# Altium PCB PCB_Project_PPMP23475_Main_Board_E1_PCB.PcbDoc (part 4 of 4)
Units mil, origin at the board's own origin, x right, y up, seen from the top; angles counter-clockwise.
Board outline 10826.77 x 2559.06 mil, 6 copper layers (Top Layer, Signal Layer 1, Signal Layer 2, Signal Layer 3, Signal Layer 4, Bottom Layer), stack 65.535 mil thick; 162 components, 91 nets, 425 pads, 676 vias.
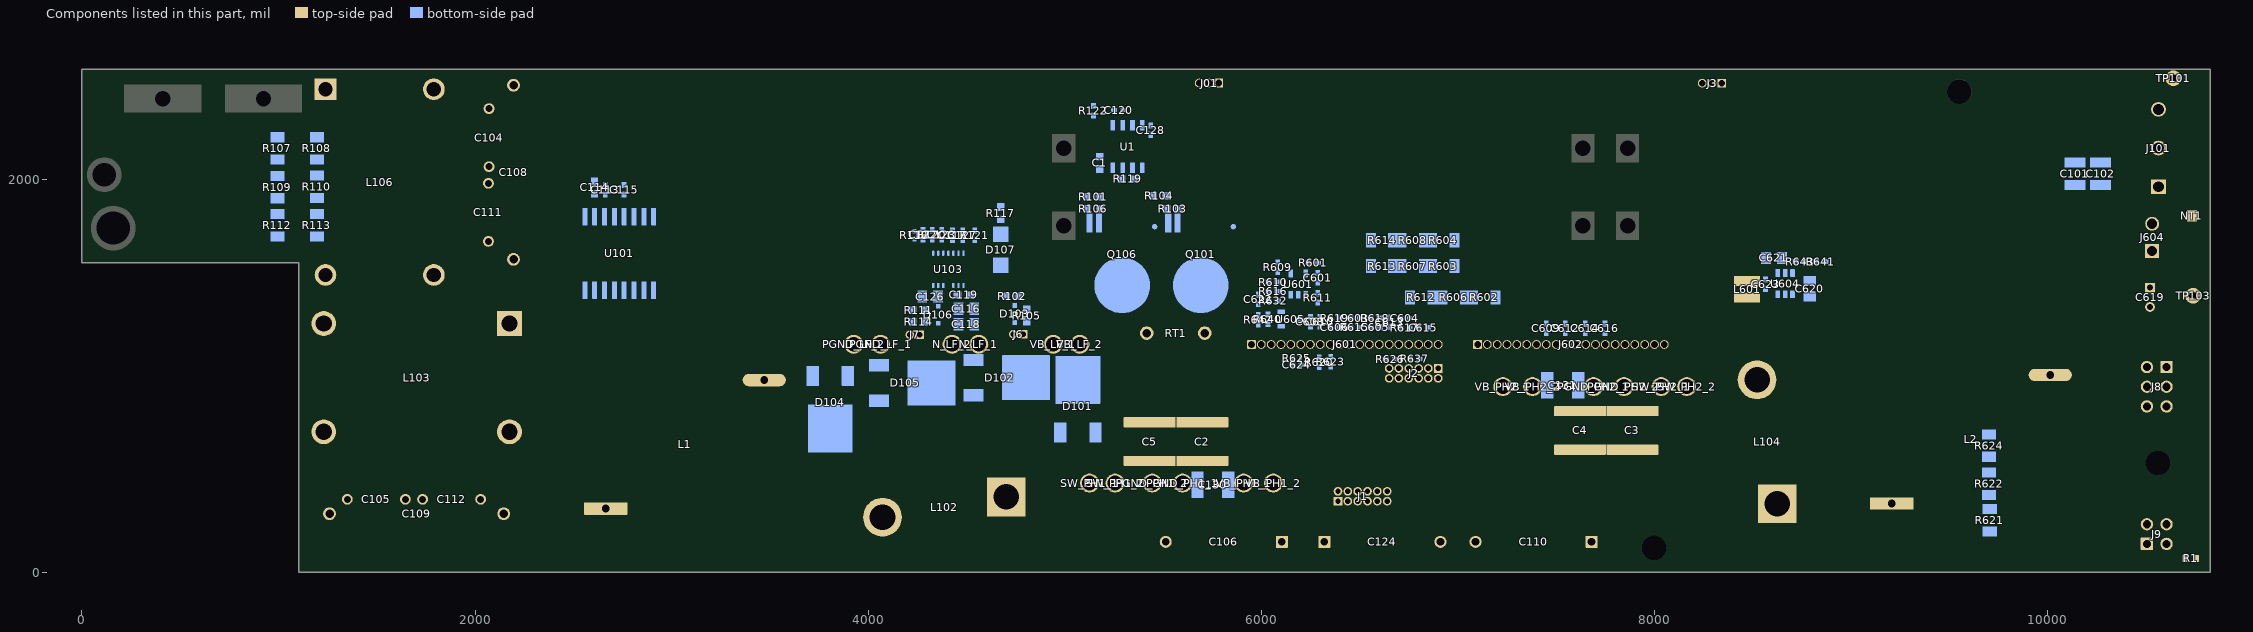
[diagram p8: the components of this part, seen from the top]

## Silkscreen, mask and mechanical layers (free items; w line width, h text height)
Top Overlay:
  circle w5: c7997,124 r118.11
  circle w5: c9551,2446 r118.11
  circle w5: c10562,557 r118.11
  lines w5: 2514.57,1350.53 5113,1350.53 5113,2571 2514.57,2571 2514.57,1350.53 ; 5155.57,1350.91 7754,1350.91 7754,2571.39 5155.57,2571.39 5155.57,1350.91 ; 7745,1350.91 10343.43,1350.91 10343.43,2571.39 7745,2571.39 7745,1350.91
  lines w7: 97.23,2214.15 97.23,2489.74 1081.48,2489.74 1081.48,1804.7 313.76,1804.7 313.76,2214.15 97.23,2214.15 ; 2336.34,24.39 2336.34,1323.61 3753.66,1323.61 3753.66,24.39 2336.34,24.39 ; 8909.88,24.17 8909.88,1323.38 10327.2,1323.38 10327.2,24.17 8909.88,24.17
  lines w10: 316.8,1744.02 cw(c159.52,1752) 317,1752 ; 3239,0.83 4990.97,0.83 4990.97,678 3239,678 3239,0.83 ; 3777.22,28.68 3777.22,638.91 4997.69,638.91 4997.69,28.68 3777.22,28.68 ; 5066,303 6701,303 6701,1052 5066,1052 5066,303 ; 6589,349 6589,1098 8224,1098 8224,349 6589,349 ; 8268.09,54.22 8878.32,54.22 8878.32,1274.69 8268.09,1274.69 8268.09,54.22 ; 8283,58.83 8283,736 10034.97,736 10034.97,58.83 8283,58.83
  text "+" at 10824,2341 h50 r90
  text "475V 5kW" at 10815,2046 h30 r90
  text "-" at 10822.99,1930 h50 r90
  text "-" at 10783.99,1785 h50 r90
  text "PMP40988" at 351,1697 h30
  text "12VAUX" at 10715,1619 h30 r90
  text "Rev: E3" at 351,1608 h30
  text "+" at 10773.33,1577 h50 r90
  text "Heat Sink this side" at 3858,734 h60
  text ".Layer_Name" at 577,-2658.49 h30
Bottom Overlay:
  lines w5: 6500,834 6510,844 ; 6510,827 6510,844 ; 6520,834 6510,844 ; 6219,1212 6219,1332 6674.5,1332 6674.5,1212 6219,1212 ; 6240,701 6240,825 6733,825 6733,701 6240,701
  text "GND" at 7808,750 h30
  text "SW2" at 8197,744 h30
  text "VB" at 7249.65,737.99 h30
  text "VB" at 6041,567 h30
  text "SW1" at 5236,556 h30
  text "GND" at 5549,553 h30
  text ".Layer_Name" at 577,-2658.49 h30
Top Paste:
  text ".Layer_Name" at 577,-2658.49 h30
Bottom Paste:
  text ".Layer_Name" at 577,-2658.49 h30
Top Solder:
  text ".Layer_Name" at 577,-2658.49 h30
  text ".Layer_Name" at 577,-2658.49 h30
Bottom Solder:
  text ".Layer_Name" at 577,-2658.49 h30
Drill Guide:
  text ".Layer_Name" at 577,-2658.49 h30
M1 Board Outline:
  the board outline again, w7.01
  text ".Layer_Name" at 577,-2658.49 h30
M2 Board Dimensions:
  rectangle: 0,-2075 125,-1950
  rectangle: 125,-2200 500,-2075
  lines w7: 0,-2075 1000,-2075 ; 125,-2200 125,-1950 ; 250,-2200 250,-1950 ; 500,-2200 500,-1950 ; 750,-2200 750,-1950 ; 0,-2200 1000,-2200 1000,-1950 0,-1950 0,-2200
  text ".Layer_Name" at 577,-2658.49 h30
M3 3D STEP Top:
  text ".Layer_Name" at 577,-2658.49 h30
M4 3D STEP Bottom:
  text ".Layer_Name" at 577,-2658.49 h30
M5 Assembly Top:
  lines w10: -292,-2730.17 6308,-2730.17 ; -292,-2526.83 6310,-2526.83 ; -292,-2323.5 -292,-2933.5 3713,-2933.5 6310,-2933.5 6310,-2323.5 -291.5,-2323.5 -291.5,-2933.5 1284,-2933.5 ; 2173,-2933.5 2173,-2323.5 ; 3440,-2526.83 3440,-2323.5 ; 4280,-2526.83 4280,-2323.5 ; 4902,-2940 4902,-2737.17
  text "COMPONENTS MARKED 'DNP' SHOULD NOT BE POPULATED." at 1153.5,-2118.5 h30
  text "ASSEMBLY VARIANT:" at 1153,-2234 h30
  text ".VariantName" at 2189,-2234 h30
  text "PCB VIEWED FROM TOP SIDE" at -228.5,-2455.67 h30
  text "BOARD #:" at 2248,-2455.67 h30
  text ".PRJ_Number" at 2793.5,-2455.67 h30
  text "REV:" at 3638,-2455.67 h30
  text ".PCB_Rev" at 3929.5,-2455.67 h30
  text "SVN REV:" at 4476,-2455.67 h30
  text ".VersionControl_RevNumber" at 4982,-2455.67 h30
  text "TID #:" at 2248,-2659 h30
  text ".TID" at 2793.5,-2659 h30
  text "PLOT NAME =" at -228.5,-2864.34 h30
  text ".plot_File_Name" at 577,-2864.34 h30
  text "GENERATED    :" at 2250,-2864.34 h30
  text ".Print_Date" at 3119.5,-2864.34 h30
  text ".Print_Time" at 3848.5,-2864.34 h30
  text "TEXAS INSTRUMENTS" at 5113,-2864.34 h30
M6 Assembly Bottom:
  lines w10: -292.5,-2527.33 6309.5,-2527.33 ; -290.5,-2730.67 6309.5,-2730.67 ; 1115.5,-2940.5 1115.5,-2737.67 ; 1737.5,-2527.33 1737.5,-2324 ; 2577.5,-2527.33 2577.5,-2324 ; 3844.5,-2934 3844.5,-2324 ; 4733.5,-2934 6309,-2934 6309,-2324 -292.5,-2324 -292.5,-2934 2304.5,-2934 6309.5,-2934 6309.5,-2324
  text "COMPONENTS MARKED 'DNP' SHOULD NOT BE POPULATED." at 6102,-2118 h30
  text ".VariantName" at 5058,-2234 h30
  text "ASSEMBLY VARIANT:" at 6097,-2234 h30
  text ".VersionControl_RevNumber" at 1035.5,-2456.17 h30
  text "SVN REV:" at 1541.5,-2456.17 h30
  text ".PCB_Rev" at 2088,-2456.17 h30
  text "REV:" at 2379.5,-2456.17 h30
  text ".PRJ_Number" at 3224,-2456.17 h30
  text "BOARD #:" at 3769.5,-2456.17 h30
  text "PCB VIEWED FROM BOTTOM SIDE" at 6246,-2456.17 h30
  text ".TID" at 3224,-2659.5 h30
  text "TID #:" at 3769.5,-2659.5 h30
  text "TEXAS INSTRUMENTS" at 904.5,-2864.84 h30
  text ".Print_Time" at 2169,-2864.84 h30
  text ".Print_Date" at 2898,-2864.84 h30
  text "GENERATED    :" at 3767.5,-2864.84 h30
  text ".plot_File_Name" at 5440.5,-2864.84 h30
  text "PLOT NAME =" at 6246,-2864.84 h30
M9 Title Sheet:
  drawing of 57 lines, arcs and shapes, not listed
  text "1" at 739.84,6236.5 h30
  text "2" at 3235.5,6236.5 h30
  text "3" at 5724.84,6236.5 h30
  text "4" at 8231.51,6236.5 h30
  text "5" at 10730.5,6236.5 h30
  text "6" at 13235.5,6236.5 h30
  text "A" at -416.5,5093.5 h30
  text "A" at 14383.5,5093.5 h30
  text "B" at -416.5,2713.5 h30
  text "B" at 14383.5,2713.5 h30
  text "C" at -416.5,338.5 h30
  text "C" at 14383.5,338.5 h30
  text "PROJECT TITLE:" at 11343.5,-1522.5 h30
  text ".PRJ_Title" at 11393.5,-1655.83 h30
  text "DESIGNED FOR:" at 11343.5,-1823.5 h30
  text ".PRJ_Customer" at 11393.5,-1963.5 h30
  text "D" at -416.5,-2031.5 h30
  text "D" at 14383.5,-2031.5 h30
  text "FILE NAME:" at 11343.5,-2123.5 h30
  text ".PCB_File_Name_No_Path" at 11393.5,-2243.5 h30
  text "Texas Instruments (TI) and/or its licensors do not warrant the accuracy or completeness of this specification" at 6374,-2405.34 h30
  text "ENGINEER:" at 11343.5,-2413.5 h30
  text "LAYOUT BY:" at 12848.5,-2413.5 h30
  text "or any information contained therein. TI and/or its licensors do not warrant that this design will meet" at 6329.01,-2518 h30
  text ".PRJ_Engineer" at 11393.5,-2568.49 h30
  text ".PCB_Layout" at 12899,-2568.49 h30
  text "the specifications, will be suitable for your application or fit for any particular purpose, or will operate in" at 6329.01,-2630.67 h30
  text ".Layer_Name" at 577,-2658.49 h30
  text "ALTIUM DESIGNER VERSION:" at 12848.5,-2723.5 h30
  text "an implementation. TI and/or its licensors do not warrant that the design is production worthy. You should" at 6329.01,-2743.33 h30
  text "completely validate and test your design implementation to confirm the system functionality for your application." at 6374,-2856 h30
  text ".print_Scale" at 11393.5,-2856.83 h30
  text ".Application_BuildNumber" at 12899,-2856.83 h30
  text "1" at 739.84,-3063.5 h30
  text "2" at 3235.5,-3063.5 h30
  text "3" at 5724.84,-3063.5 h30
  text "4" at 8231.51,-3063.5 h30
  text "5" at 10730.5,-3063.5 h30
  text "6" at 13235.5,-3063.5 h30
M10 Fab Notes:
  drawing of 687 lines, arcs and shapes, not listed
  text "DESIGN INFORMATION" at 12033.02,5780.17 h60
  text "Layer" at 1816.58,5739 h60
  text "Name" at 2226.49,5739 h60
  text "Material" at 3166.23,5739 h60
  text "Thickness" at 4026,5739 h60
  text "Constant" at 4675.84,5739 h60
  text "Board Layer Stack" at 5245.7,5739 h60
  text "MIN. TRACK WIDTH:" at 11388.46,5648.05 h60
  text "8" at 12484.7,5648.05 h60
  text "MIL" at 12639.46,5648.05 h60
  text "Top Overlay" at 2226.49,5619 h60
  text "7.874" at 12318.32,5526.36 h60
  text "MIN. CLEARANCE:" at 11388.46,5523.92 h60
  text "MIL" at 12639.46,5523.92 h60
  text "Top Solder" at 2226.49,5499 h60
  text "Solder Resist" at 3166.23,5499 h60
  text "0.40mil" at 4026,5499 h60
  text "3.5" at 4675.84,5499 h60
  text "MIN. VIA PAD SIZE:" at 11388.46,5399.8 h60
  text "24" at 12454.71,5399.8 h60
  text "MIL" at 12639.46,5399.8 h60
  text "1" at 1816.58,5379 h60
  text "Top Layer" at 2226.49,5379 h60
  text "2.76mil" at 4026,5379 h60
  text "0.05mm (2MIL)" at 12083.46,5269.9 h60
  text "MINIMUM ANNULAR RING" at 11059.23,5261.67 h60
  text "EXTERNAL" at 12791.46,5261.67 h60
  text "Dielectric1" at 2226.49,5259 h60
  text "7.00mil" at 4026,5259 h60
  text "4.2" at 4675.84,5259 h60
  text "PER" at 11259.23,5151.55 h60
  text "IPC-D-275 CLASS 2 LEVEL C" at 11479.23,5151.54 h60
  text "2" at 1816.58,5139 h60
  text "Signal Layer 1" at 2226.49,5139 h60
  text "2.76mil" at 4026,5139 h60
  text "MIL, HOLES" at 12967.46,5051.07 h60
  text "+/-" at 12575,5042.48 h60
  text "+/-" at 13429,5042.48 h60
  text "REGISTRATION TOLERANCES:" at 11059.23,5041.42 h60
  text "METAL" at 12259,5041.42 h60
  text "5" at 12835.2,5041.42 h60
  text "3" at 13668.2,5041.42 h60
  text "MIL" at 13784.46,5041.42 h60
  text "Dielectric 3" at 2226.49,5019 h60
  text "FR-4" at 3166.23,5019 h60
  text "14.00mil" at 4026,5019 h60
  text "4.2" at 4675.84,5019 h60
  text "HOLE SIZE TOLERANCE (UNLESS OTHERWISE SPECIFIED):" at 11059.23,4943.1 h60
  text "+/-" at 13429,4940.23 h60
  text "3" at 13668.2,4939.17 h60
  text "MIL" at 13784.46,4939.17 h60
  text "3" at 1816.58,4899 h60
  text "Signal Layer 2" at 2226.49,4899 h60
  text "2.76mil" at 4026,4899 h60
  text "MATERIAL:" at 10984.46,4801.52 h60
  text "Dielectric 4" at 2226.49,4779 h60
  text "7.00mil" at 4026,4779 h60
  text "4.2" at 4675.84,4779 h60
  text "FR-4 High Tg" at 11970.9,4673 h60
  text "X" at 11826.46,4665.01 h60
  text "FR-408" at 11405.46,4660.49 h60
  text "OTHER" at 12893.46,4660.49 h60
  text "4" at 1816.58,4659 h60
  text "Signal Layer 3" at 2226.49,4659 h60
  text "2.76mil" at 4026,4659 h60
  text "Dielectric 5" at 2226.49,4539 h60
  text "FR-4" at 3166.23,4539 h60
  text "14.00mil" at 4026,4539 h60
  text "4.2" at 4675.84,4539 h60
  text "62 MIL (1.6mm) +/-10%" at 11725.56,4517.46 h60
  text "X" at 11605.46,4515.01 h60
  text "THICKNESS:" at 11059.23,4509.24 h60
  text "OTHER" at 13010.46,4509.24 h60
  text "5" at 1816.58,4419 h60
  text "Signal Layer 4" at 2226.49,4419 h60
  text "2.76mil" at 4026,4419 h60
  text "TOLERANCE:" at 11059.23,4370.92 h60
  text "X" at 11907.46,4370.92 h60
  text "ANSI IPC-6012 TYPE 3 CLASS 2" at 12085.48,4370.92 h60
  text "Dielectric 2" at 2226.49,4299 h60
  text "7.00mil" at 4026,4299 h60
  text "4.2" at 4675.84,4299 h60
  text "OTHER +/-" at 12085.46,4226.73 h60
  text "6" at 1816.58,4179 h60
  text "Bottom Layer" at 2226.49,4179 h60
  text "2.76mil" at 4026,4179 h60
  text "BOW & TWIST:" at 11059.23,4081.54 h60
  text "X" at 11907.46,4081.54 h60
  text "ANSI IPC-6012 TYPE 3 CLASS 2" at 12085.48,4081.54 h60
  text "Bottom Solder" at 2226.49,4059 h60
  text "Solder Resist" at 3166.23,4059 h60
  text "0.40mil" at 4026,4059 h60
  text "3.5" at 4675.84,4059 h60
  text "Bottom Overlay" at 2226.49,3939 h60
  text "OTHER +/-" at 12085.46,3934.85 h60
  text "DRILLING:" at 10984.46,3804.23 h60
  text "NC_DRILL FILES" at 12745.46,3699.04 h60
  text "REFERENCE:" at 11059.23,3695.1 h60
  text "X" at 11716.46,3695.01 h60
  text "AS SHOWN" at 11894.46,3695.1 h60
  text "X" at 12617.46,3695.1 h60
  text "OTHER" at 13043.46,3552.85 h60
  text "PTH COPPER THICKNESS:" at 11058.91,3549.32 h60
  text "X" at 12198.14,3549.32 h60
  text "20-30 um" at 12326.14,3549.32 h60
  text "BOARD FINISH:" at 10984.46,3401.73 h60
  text "SILKSCREEN:" at 11139.68,3291.6 h60
  text "X" at 12097.46,3291.6 h60
  text "TOP" at 12214.46,3291.6 h60
  text "X" at 12607.46,3291.6 h60
  text "BOTTOM" at 12725.46,3291.6 h60
  text "SILKSCREEN COLOR:" at 11139.68,3136.41 h60
  text "X" at 12096.46,3136.41 h60
  text "WHITE" at 12214.46,3136.41 h60
  text "OTHER" at 12725.46,3136.41 h60
  text "X" at 12227.46,2992.96 h60
  text "GREEN" at 12345.46,2992.96 h60
  text "OTHER" at 12963.46,2992.96 h60
  text "SOLDER RESIST COLOR:" at 11139.68,2986.1 h60
  text "X" at 12227.46,2838.71 h60
  text "MATTE" at 12345.46,2838.71 h60
  text "SEMI-GLOSS" at 12963,2838.07 h60
  text "IMMERSION GOLD (ENIG)" at 12045.46,2665.94 h60
  text "X" at 11863,2663 h60
  text "ENEPIG" at 13383,2658.72 h60
  text "SURFACE FINISH:" at 10984.46,2657.72 h60
  text "IMM. TIN/SILVER OR EQUIV" at 11314,2520.4 h60
  text "OTHER" at 12745.46,2516.47 h60
  text "ARRAY/PANEL:" at 10984.46,2361.09 h60
  text "CUT AND TRIM PER M1 BOARD OUTLINE" at 12045.46,2352.87 h60
  text "N.C. ROUTE" at 12045.46,2216.9 h60
  text "X" at 12733.46,2216.9 h60
  text "V. SCORE" at 12911.46,2216.9 h60
  text "CERTIFICATION:" at 10984.46,2087.77 h60
  text "MATERIALS AND WORKMANSHIP FOR ALL PCBS" at 11709.46,2087.77 h60
  text "TO MEET OR EXCEED THE REQUIREMENTS OF:" at 11709.46,1993.71 h60
  text "X" at 11346.97,1865.08 h60
  text "ANSI IPC-A-600F CLASS ->" at 11474.96,1865.08 h60
  text "X" at 13122.97,1865.08 h60
  text "2" at 13232.96,1865.08 h60
  text "1" at 12917.96,1863.58 h60
  text "3" at 13586.96,1863.58 h60
  text "X" at 12158.97,1717.39 h60
  text "RoHS" at 12286.96,1717.39 h60
  text "OTHER" at 12931.36,1717.39 h60
  text "PER ORDER" at 13328.42,1717.39 h60
  text "ALL BOARDS MUST MEET OR EXCEED UL94-V0 REQUIREMENTS." at 11012,1563.57 h60
  text "PCB MUST BEAR THE UL94V-0 UL REGISTERED MATERIAL ID NUMBER" at 11012,1447.5 h60
  text "ADDITIONAL REQUIREMENTS:" at 10984.46,1278.08 h60
  text "MICROSECTION:" at 11059.23,1170.95 h60
  text "YES" at 11964.96,1170.95 h60
  text "REQUIRED" at 12826.46,1026.62 h60
  text "BARE BOARD ELEC. TEST:" at 11059.23,1023.76 h60
  text "NONE" at 12364.96,1023.76 h60
  text "PER ORDER" at 13418.46,1023.76 h60
  text "X" at 12712,1023 h60
  text "XX MIL VIAS REQUIRE NON-CONDUCTIVE FILL AND PLANARIZE" at 11227.38,818.82 h59
  text "XX MIL VIAS REQUIRE CONDUCTIVE FILL AND PLANARIZE" at 11235.38,714.84 h60
  text "OUTER XX MIL TRACES REQUIRE 50 OHM SINGLE-ENDED IMPEDANCE" at 11234.39,551.46 h58
  text "LAYER 2 & 3 (INNER LAYERS) XX MIL WIDE, XX MIL SPACE / TRACES REQUIRE 100 OHM DIFFERENTIAL IMPEDANCE" at 11226.39,315.74 h60
  text ".Layer_Name" at 577,-2658.49 h30
M11 Gerber Information:
  lines w10: -292,-2730.17 6308,-2730.17 ; -292,-2526.83 6310,-2526.83 ; -292,-2323.5 -292,-2933.5 3713,-2933.5 6310,-2933.5 6310,-2323.5 -291.5,-2323.5 -291.5,-2933.5 1284,-2933.5 ; 2173,-2933.5 2173,-2323.5 ; 3440,-2526.83 3440,-2323.5 ; 4280,-2526.83 4280,-2323.5 ; 4902,-2940 4902,-2737.17
  text "ALL ARTWORK VIEWED FROM TOP SIDE" at -228.5,-2455.67 h30
  text "BOARD #:" at 2248,-2455.67 h30
  text ".PRJ_Number" at 2793.5,-2455.67 h30
  text "REV:" at 3638,-2455.67 h30
  text ".PCB_Rev" at 3929.5,-2455.67 h30
  text "SVN REV:" at 4476,-2455.67 h30
  text ".VersionControl_RevNumber" at 4982,-2455.67 h30
  text "LAYER NAME =" at -228.5,-2658.49 h30
  text "TID #:" at 2248,-2659 h30
  text ".TID" at 2793.5,-2659 h30
  text "PLOT NAME =" at -228.5,-2864.34 h30
  text ".plot_File_Name" at 577,-2864.34 h30
  text "GENERATED    :" at 2250,-2864.34 h30
  text ".Print_Date" at 3119.5,-2864.34 h30
  text ".Print_Time" at 3848.5,-2864.34 h30
  text "TEXAS INSTRUMENTS" at 5113,-2864.34 h30
M12 Stackup:
  drawing of 399 lines, arcs and shapes, not listed
  text "Layer" at 6593.35,5039 h30
  text "Name" at 6808.3,5039 h30
  text "Material" at 7288.17,5039 h30
  text "Thickness" at 7728.06,5039 h30
  text "Constant" at 8062.97,5039 h30
  text "Board Layer Stack" at 8357.9,5039 h30
  text "Top Overlay" at 6808.3,4979 h30
  text "Top Solder" at 6808.3,4919 h30
  text "Solder Resist" at 7288.17,4919 h30
  text "0.40mil" at 7728.06,4919 h30
  text "3.5" at 8062.97,4919 h30
  text "1" at 6593.35,4859 h30
  text "Top Layer" at 6808.3,4859 h30
  text "2.76mil" at 7728.06,4859 h30
  text "Dielectric1" at 6808.3,4799 h30
  text "7.00mil" at 7728.06,4799 h30
  text "4.2" at 8062.97,4799 h30
  text "2" at 6593.35,4739 h30
  text "Signal Layer 1" at 6808.3,4739 h30
  text "2.76mil" at 7728.06,4739 h30
  text "Dielectric 3" at 6808.3,4679 h30
  text "FR-4" at 7288.17,4679 h30
  text "14.00mil" at 7728.06,4679 h30
  text "4.2" at 8062.97,4679 h30
  text "3" at 6593.35,4619 h30
  text "Signal Layer 2" at 6808.3,4619 h30
  text "2.76mil" at 7728.06,4619 h30
  text "Dielectric 4" at 6808.3,4559 h30
  text "7.00mil" at 7728.06,4559 h30
  text "4.2" at 8062.97,4559 h30
  text "4" at 6593.35,4499 h30
  text "Signal Layer 3" at 6808.3,4499 h30
  text "2.76mil" at 7728.06,4499 h30
  text "Dielectric 5" at 6808.3,4439 h30
  text "FR-4" at 7288.17,4439 h30
  text "14.00mil" at 7728.06,4439 h30
  text "4.2" at 8062.97,4439 h30
  text "5" at 6593.35,4379 h30
  text "Signal Layer 4" at 6808.3,4379 h30
  text "2.76mil" at 7728.06,4379 h30
  text "Dielectric 2" at 6808.3,4319 h30
  text "7.00mil" at 7728.06,4319 h30
  text "4.2" at 8062.97,4319 h30
  text "6" at 6593.35,4259 h30
  text "Bottom Layer" at 6808.3,4259 h30
  text "2.76mil" at 7728.06,4259 h30
  text "Bottom Solder" at 6808.3,4199 h30
  text "Solder Resist" at 7288.17,4199 h30
  text "0.40mil" at 7728.06,4199 h30
  text "3.5" at 8062.97,4199 h30
  text "Bottom Overlay" at 6808.3,4139 h30
  text ".Layer_Name" at 577,-2658.49 h30
M13 Component Bodies Top:
  text ".Layer_Name" at 577,-2658.49 h30
M14 Component Bodies Bottom:
  text ".Layer_Name" at 577,-2658.49 h30
M15 Courtyards Top:
  text ".Layer_Name" at 577,-2658.49 h30
M16 Courtyards Bottom:
  text ".Layer_Name" at 577,-2658.49 h30
Drill Drawing:
  drawing of 375 lines, arcs and shapes, not listed
  text "Symbol" at 43.65,5515.19 h36
  text "Quantity" at 193.91,5515.19 h36
  text "Finished Hole Size" at 359.89,5515.19 h36
  text "Plated" at 678.15,5515.19 h36
  text "Hole Type" at 807.7,5515.19 h36
  text "Drill Layer Pair" at 995.26,5515.19 h36
  text "Tolerance" at 1356.56,5515.19 h36
  text "666" at 193.91,5453.06 h30
  text "0.254mm (10.00mil)" at 359.89,5453.06 h30
  text "PTH" at 678.15,5453.06 h30
  text "Round" at 807.7,5453.06 h30
  text "Top Layer - Bottom Layer" at 995.26,5453.06 h30
  text "10" at 193.91,5390.94 h30
  text "0.406mm (16.00mil)" at 359.89,5390.94 h30
  text "PTH" at 678.15,5390.94 h30
  text "Round" at 807.7,5390.94 h30
  text "Top Layer - Bottom Layer" at 995.26,5390.94 h30
  text "28" at 193.91,5328.82 h30
  text "0.700mm (27.56mil)" at 359.89,5328.82 h30
  text "PTH" at 678.15,5328.82 h30
  text "Round" at 807.7,5328.82 h30
  text "Top Layer - Bottom Layer" at 995.26,5328.82 h30
  text "A" at 27.58,5318.82 h27.61
  text "2" at 193.91,5266.7 h30
  text "0.750mm (29.53mil)" at 359.89,5266.7 h30
  text "PTH" at 678.15,5266.7 h30
  text "Round" at 807.7,5266.7 h30
  text "Top Layer - Bottom Layer" at 995.26,5266.7 h30
  text "D" at 27.58,5256.7 h27.61
  text "46" at 193.91,5204.57 h30
  text "0.850mm (33.47mil)" at 359.89,5204.57 h30
  text "PTH" at 678.15,5204.57 h30
  text "Round" at 807.7,5204.57 h30
  text "Top Layer - Bottom Layer" at 995.26,5204.57 h30
  text "L" at 27.58,5194.58 h27.61
  text "8" at 193.91,5142.45 h30
  text "0.900mm (35.43mil)" at 359.89,5142.45 h30
  text "PTH" at 678.15,5142.45 h30
  text "Round" at 807.7,5142.45 h30
  text "Top Layer - Bottom Layer" at 995.26,5142.45 h30
  text "6" at 193.91,5080.33 h30
  text "1.000mm (39.37mil)" at 359.89,5080.33 h30
  text "PTH" at 678.15,5080.33 h30
  text "Round" at 807.7,5080.33 h30
  text "Top Layer - Bottom Layer" at 995.26,5080.33 h30
  text "2" at 193.91,5018.2 h30
  text "1.016mm (40.00mil)" at 359.89,5018.2 h30
  text "PTH" at 678.15,5018.2 h30
  text "Round" at 807.7,5018.2 h30
  text "Top Layer - Bottom Layer" at 995.26,5018.2 h30
  text "10" at 193.91,4956.08 h30
  text "1.040mm (40.95mil)" at 359.89,4956.08 h30
  text "PTH" at 678.15,4956.08 h30
  text "Round" at 807.7,4956.08 h30
  text "Top Layer - Bottom Layer" at 995.26,4956.08 h30
  text "6" at 193.91,4893.96 h30
  text "1.100mm (43.31mil)" at 359.89,4893.96 h30
  text "PTH" at 678.15,4893.96 h30
  text "Round" at 807.7,4893.96 h30
  text "Top Layer - Bottom Layer" at 995.26,4893.96 h30
  text "2" at 193.91,4831.83 h30
  text "1.300mm (51.18mil)" at 359.89,4831.83 h30
  text "PTH" at 678.15,4831.83 h30
  text "Round" at 807.7,4831.83 h30
  text "Top Layer - Bottom Layer" at 995.26,4831.83 h30
  text "B" at 27.58,4821.84 h27.61
  text "3" at 193.91,4769.71 h30
  text "1.400mm (55.12mil)" at 359.89,4769.71 h30
  text "PTH" at 678.15,4769.71 h30
  text "Round" at 807.7,4769.71 h30
  text "Top Layer - Bottom Layer" at 995.26,4769.71 h30
  text "4" at 193.91,4707.59 h30
  text "1.850mm (72.84mil)" at 359.89,4707.59 h30
  text "PTH" at 678.15,4707.59 h30
  text "Round" at 807.7,4707.59 h30
  text "Top Layer - Bottom Layer" at 995.26,4707.59 h30
  text "18" at 193.91,4645.47 h30
  text "1.905mm (75.00mil)" at 359.89,4645.47 h30
  text "PTH" at 678.15,4645.47 h30
  text "Round" at 807.7,4645.47 h30
  text "Top Layer - Bottom Layer" at 995.26,4645.47 h30
  text "K" at 27.58,4635.47 h27.61
  text "4" at 193.91,4583.34 h30
  text "2.100mm (82.68mil)" at 359.89,4583.34 h30
  text "PTH" at 678.15,4583.34 h30
  text "Round" at 807.7,4583.34 h30
  text "Top Layer - Bottom Layer" at 995.26,4583.34 h30
  text "1" at 193.91,4521.22 h30
  text "3.000mm (118.11mil)" at 359.89,4521.22 h30
  text "PTH" at 678.15,4521.22 h30
  text "Round" at 807.7,4521.22 h30
  text "Top Layer - Bottom Layer" at 995.26,4521.22 h30
  text "3" at 193.91,4459.1 h30
  text "3.200mm (125.98mil)" at 359.89,4459.1 h30
  text "PTH" at 678.15,4459.1 h30
  text "Round" at 807.7,4459.1 h30
  text "Top Layer - Bottom Layer" at 995.26,4459.1 h30
  text "I" at 32.18,4449.1 h27.61
  text "4" at 193.91,4396.97 h30
  text "3.300mm (129.92mil)" at 359.89,4396.97 h30
  text "PTH" at 678.15,4396.97 h30
  text "Round" at 807.7,4396.97 h30
  text "Top Layer - Bottom Layer" at 995.26,4396.97 h30
  text "M" at 27.58,4386.98 h27.61
  text "1" at 193.91,4334.85 h30
  text "4.300mm (169.29mil)" at 359.89,4334.85 h30
  text "PTH" at 678.15,4334.85 h30
  text "Round" at 807.7,4334.85 h30
  text "Top Layer - Bottom Layer" at 995.26,4334.85 h30
  text "6" at 193.91,4272.73 h30
  text "2.000mm (78.74mil)" at 359.89,4272.73 h30
  text "PTH" at 678.15,4272.73 h30
  text "Rectangle" at 807.7,4272.73 h30
  text "Top Layer - Bottom Layer" at 995.26,4272.73 h30
  text "2" at 193.91,4210.6 h30
  text "2.000mm (78.74mil)" at 359.89,4210.6 h30
  text "PTH" at 678.15,4210.6 h30
  text "Rectangle" at 807.7,4210.6 h30
  text "Top Layer - Bottom Layer" at 995.26,4210.6 h30
  text "4" at 193.91,4148.48 h30
  text "1.000mm (39.37mil)" at 359.89,4148.48 h30
  text "PTH" at 678.15,4148.48 h30
  text "Slot" at 807.7,4148.48 h30
  text "Top Layer - Bottom Layer" at 995.26,4148.48 h30
  text "836 Total" at 193.91,4086.36 h30
  text "Slot definitions :" at 43.65,4042.87 h30
  text "Routed Path Length" at 268.47,4042.87 h30
  text "= Calculated from tool start centre position to tool end centre position." at 537.62,4042.87 h30
  text "Hole Length" at 268.47,4018.02 h30
  text "= Routed Path Length + Tool Size = Slot length as defined in the PCB layout" at 437.98,4018.02 h30
  text "Symbol" at 3848.21,-426.49 h29.46
  text "Count" at 4074.1,-426.49 h29.46
  text "Hole Size" at 4331.36,-426.49 h29.46
  text "Plated" at 4813.59,-426.49 h29.46
  text "Hole Type" at 5039.49,-426.49 h29.46
  text "Drill Layer Pair" at 5358.64,-426.49 h29.46
  text "Via/Pad" at 5984.04,-426.49 h29.46
  text "Pad Shape" at 6244.29,-426.49 h29.46
  text "Template" at 6701.98,-426.49 h29.46
  text "Description" at 7163.76,-426.49 h29.46
  text "Hole Tolerance (+)" at 7532,-426.49 h29.46
  text "Hole Tolerance (-)" at 8096.58,-426.49 h29.46
  text "Hole Length" at 8661.17,-426.49 h29.46
  text "Routed Path Length" at 9147.48,-426.49 h29.46
  text "1" at 4074.1,-487.86 h24.55
  text "118.11mil (3.000mm)" at 4331.36,-487.86 h24.55
  text "PTH" at 4813.59,-487.86 h24.55
  text "Round" at 5039.49,-487.86 h24.55
  text "Top Layer - Bottom Layer" at 5358.64,-487.86 h24.55
  text "Pad" at 5984.04,-487.86 h24.55
  text "Rounded" at 6244.29,-487.86 h24.55
  text "c450h300" at 6701.98,-487.86 h24.55
  text "-" at 8661.17,-487.86 h24.55
  text "-" at 9147.48,-487.86 h24.55
  text "1" at 4074.1,-549.24 h24.55
  text "169.29mil (4.300mm)" at 4331.36,-549.24 h24.55
  text "PTH" at 4813.59,-549.24 h24.55
  text "Round" at 5039.49,-549.24 h24.55
  text "Top Layer - Bottom Layer" at 5358.64,-549.24 h24.55
  text "Pad" at 5984.04,-549.24 h24.55
  text "Rounded" at 6244.29,-549.24 h24.55
  text "c580h430" at 6701.98,-549.24 h24.55
  text "-" at 8661.17,-549.24 h24.55
  text "-" at 9147.48,-549.24 h24.55
  text "2" at 4074.1,-610.62 h24.55
  text "29.53mil (0.750mm)" at 4331.36,-610.62 h24.55
  text "PTH" at 4813.59,-610.62 h24.55
  text "Round" at 5039.49,-610.62 h24.55
  text "Top Layer - Bottom Layer" at 5358.64,-610.62 h24.55
  text "Pad" at 5984.04,-610.62 h24.55
  text "(Mixed)" at 6244.29,-610.62 h24.55
  text "(Mixed)" at 6701.98,-610.62 h24.55
  text "-" at 8661.17,-610.62 h24.55
  text "-" at 9147.48,-610.62 h24.55
  text "D" at 3832.24,-620.61 h27.28
  text "2" at 4074.1,-671.99 h24.55
  text "40.00mil (1.016mm)" at 4331.36,-671.99 h24.55
  text "PTH" at 4813.59,-671.99 h24.55
  text "Round" at 5039.49,-671.99 h24.55
  text "Top Layer - Bottom Layer" at 5358.64,-671.99 h24.55
  text "Pad" at 5984.04,-671.99 h24.55
  text "Rounded" at 6244.29,-671.99 h24.55
  text "c203h102" at 6701.98,-671.99 h24.55
  text "-" at 8661.17,-671.99 h24.55
  text "-" at 9147.48,-671.99 h24.55
  text "2" at 4074.1,-733.37 h24.55
  text "51.18mil (1.300mm)" at 4331.36,-733.37 h24.55
  text "PTH" at 4813.59,-733.37 h24.55
  text "Round" at 5039.49,-733.37 h24.55
  text "Top Layer - Bottom Layer" at 5358.64,-733.37 h24.55
  text "Pad" at 5984.04,-733.37 h24.55
  text "(Mixed)" at 6244.29,-733.37 h24.55
  text "(Mixed)" at 6701.98,-733.37 h24.55
  text "-" at 8661.17,-733.37 h24.55
  text "-" at 9147.48,-733.37 h24.55
  text "B" at 3832.24,-743.36 h27.28
  text "2" at 4074.1,-794.74 h24.55
  text "78.74mil (2.000mm)" at 4331.36,-794.74 h24.55
  text "PTH" at 4813.59,-794.74 h24.55
  text "Rectangle" at 5039.49,-794.74 h24.55
  text "Top Layer - Bottom Layer" at 5358.64,-794.74 h24.55
  text "Pad" at 5984.04,-794.74 h24.55
  text "Rectangle" at 6244.29,-794.74 h24.55
  text "r1000_360h200_880" at 6701.98,-794.74 h24.55
  text "346.46mil (8.800mm)" at 8661.17,-794.74 h24.55
  text "346.46mil (8.800mm)" at 9147.48,-794.74 h24.55
  text "3" at 4074.1,-856.12 h24.55
  text "55.12mil (1.400mm)" at 4331.36,-856.12 h24.55
  text "PTH" at 4813.59,-856.12 h24.55
  text "Round" at 5039.49,-856.12 h24.55
  text "Top Layer - Bottom Layer" at 5358.64,-856.12 h24.55
  text "Pad" at 5984.04,-856.12 h24.55
  text "(Mixed)" at 6244.29,-856.12 h24.55
  text "(Mixed)" at 6701.98,-856.12 h24.55
  text "-" at 8661.17,-856.12 h24.55
  text "-" at 9147.48,-856.12 h24.55
  text "3" at 4074.1,-917.5 h24.55
  text "125.98mil (3.200mm)" at 4331.36,-917.5 h24.55
  text "PTH" at 4813.59,-917.5 h24.55
  text "Round" at 5039.49,-917.5 h24.55
  text "Top Layer - Bottom Layer" at 5358.64,-917.5 h24.55
  text "Pad" at 5984.04,-917.5 h24.55
  text "Rounded" at 6244.29,-917.5 h24.55
  text "c320h320" at 6701.98,-917.5 h24.55
  text "-" at 8661.17,-917.5 h24.55
  text "-" at 9147.48,-917.5 h24.55
  text "I" at 3836.79,-927.49 h27.28
  text "4" at 4074.1,-978.87 h24.55
  text "39.37mil (1.000mm)" at 4331.36,-978.87 h24.55
  text "PTH" at 4813.59,-978.87 h24.55
  text "Slot" at 5039.49,-978.87 h24.55
  text "Top Layer - Bottom Layer" at 5358.64,-978.87 h24.55
  text "Pad" at 5984.04,-978.87 h24.55
  text "Rounded Rectangle" at 6244.29,-978.87 h24.55
  text "(Mixed)" at 6701.98,-978.87 h24.55
  text "196.85mil (5.000mm)" at 8661.17,-978.87 h24.55
  text "157.48mil (4.000mm)" at 9147.48,-978.87 h24.55
  text "4" at 4074.1,-1040.25 h24.55
  text "72.84mil (1.850mm)" at 4331.36,-1040.25 h24.55
  text "PTH" at 4813.59,-1040.25 h24.55
  text "Round" at 5039.49,-1040.25 h24.55
  text "Top Layer - Bottom Layer" at 5358.64,-1040.25 h24.55
  text "Pad" at 5984.04,-1040.25 h24.55
  text "(Mixed)" at 6244.29,-1040.25 h24.55
  text "(Mixed)" at 6701.98,-1040.25 h24.55
  text "-" at 8661.17,-1040.25 h24.55
  text "-" at 9147.48,-1040.25 h24.55
  text "4" at 4074.1,-1101.62 h24.55
  text "82.68mil (2.100mm)" at 4331.36,-1101.62 h24.55
  text "PTH" at 4813.59,-1101.62 h24.55
  text "Round" at 5039.49,-1101.62 h24.55
  text "Top Layer - Bottom Layer" at 5358.64,-1101.62 h24.55
  text "Pad" at 5984.04,-1101.62 h24.55
  text "(Mixed)" at 6244.29,-1101.62 h24.55
  text "(Mixed)" at 6701.98,-1101.62 h24.55
  text "-" at 8661.17,-1101.62 h24.55
  text "-" at 9147.48,-1101.62 h24.55
  text "4" at 4074.1,-1163 h24.55
  text "129.92mil (3.300mm)" at 4331.36,-1163 h24.55
  text "PTH" at 4813.59,-1163 h24.55
  text "Round" at 5039.49,-1163 h24.55
  text "Top Layer - Bottom Layer" at 5358.64,-1163 h24.55
  text "Pad" at 5984.04,-1163 h24.55
  text "(Mixed)" at 6244.29,-1163 h24.55
  text "(Mixed)" at 6701.98,-1163 h24.55
  text "-" at 8661.17,-1163 h24.55
  text "-" at 9147.48,-1163 h24.55
  text "M" at 3832.24,-1173 h27.28
  text "6" at 4074.1,-1224.38 h24.55
  text "39.37mil (1.000mm)" at 4331.36,-1224.38 h24.55
  text "PTH" at 4813.59,-1224.38 h24.55
  text "Round" at 5039.49,-1224.38 h24.55
  text "Top Layer - Bottom Layer" at 5358.64,-1224.38 h24.55
  text "Pad" at 5984.04,-1224.38 h24.55
  text "(Mixed)" at 6244.29,-1224.38 h24.55
  text "(Mixed)" at 6701.98,-1224.38 h24.55
  text "-" at 8661.17,-1224.38 h24.55
  text "-" at 9147.48,-1224.38 h24.55
  text "6" at 4074.1,-1285.75 h24.55
  text "43.31mil (1.100mm)" at 4331.36,-1285.75 h24.55
  text "PTH" at 4813.59,-1285.75 h24.55
  text "Round" at 5039.49,-1285.75 h24.55
  text "Top Layer - Bottom Layer" at 5358.64,-1285.75 h24.55
  text "Pad" at 5984.04,-1285.75 h24.55
  text "Rounded" at 6244.29,-1285.75 h24.55
  text "(Mixed)" at 6701.98,-1285.75 h24.55
  text "-" at 8661.17,-1285.75 h24.55
  text "-" at 9147.48,-1285.75 h24.55
  text "6" at 4074.1,-1347.13 h24.55
  text "78.74mil (2.000mm)" at 4331.36,-1347.13 h24.55
  text "PTH" at 4813.59,-1347.13 h24.55
  text "Rectangle" at 5039.49,-1347.13 h24.55
  text "Top Layer - Bottom Layer" at 5358.64,-1347.13 h24.55
  text "Pad" at 5984.04,-1347.13 h24.55
  text "Rectangle" at 6244.29,-1347.13 h24.55
  text "r370_300h200_300" at 6701.98,-1347.13 h24.55
  text "118.11mil (3.000mm)" at 8661.17,-1347.13 h24.55
  text "118.11mil (3.000mm)" at 9147.48,-1347.13 h24.55
  text "8" at 4074.1,-1408.5 h24.55
  text "35.43mil (0.900mm)" at 4331.36,-1408.5 h24.55
  text "PTH" at 4813.59,-1408.5 h24.55
  text "Round" at 5039.49,-1408.5 h24.55
  text "Top Layer - Bottom Layer" at 5358.64,-1408.5 h24.55
  text "Pad" at 5984.04,-1408.5 h24.55
  text "Rounded" at 6244.29,-1408.5 h24.55
  text "c140h90" at 6701.98,-1408.5 h24.55
  text "-" at 8661.17,-1408.5 h24.55
  text "-" at 9147.48,-1408.5 h24.55
  text "10" at 4074.1,-1469.88 h24.55
  text "16.00mil (0.406mm)" at 4331.36,-1469.88 h24.55
  text "PTH" at 4813.59,-1469.88 h24.55
  text "Round" at 5039.49,-1469.88 h24.55
  text "Top Layer - Bottom Layer" at 5358.64,-1469.88 h24.55
  text "Via" at 5984.04,-1469.88 h24.55
  text "Rounded" at 6244.29,-1469.88 h24.55
  text "v86h41" at 6701.98,-1469.88 h24.55
  text "-" at 8661.17,-1469.88 h24.55
  text "-" at 9147.48,-1469.88 h24.55
  text "10" at 4074.1,-1531.26 h24.55
  text "40.95mil (1.040mm)" at 4331.36,-1531.26 h24.55
  text "PTH" at 4813.59,-1531.26 h24.55
  text "Round" at 5039.49,-1531.26 h24.55
  text "Top Layer - Bottom Layer" at 5358.64,-1531.26 h24.55
  text "Pad" at 5984.04,-1531.26 h24.55
  text "(Mixed)" at 6244.29,-1531.26 h24.55
  text "(Mixed)" at 6701.98,-1531.26 h24.55
  text "-" at 8661.17,-1531.26 h24.55
  text "-" at 9147.48,-1531.26 h24.55
  text "18" at 4074.1,-1592.63 h24.55
  text "75.00mil (1.905mm)" at 4331.36,-1592.63 h24.55
  text "PTH" at 4813.59,-1592.63 h24.55
  text "Round" at 5039.49,-1592.63 h24.55
  text "Top Layer - Bottom Layer" at 5358.64,-1592.63 h24.55
  text "Pad" at 5984.04,-1592.63 h24.55
  text "Rounded" at 6244.29,-1592.63 h24.55
  text "c245h190" at 6701.98,-1592.63 h24.55
  text "-" at 8661.17,-1592.63 h24.55
  text "-" at 9147.48,-1592.63 h24.55
  text "K" at 3832.24,-1602.63 h27.28
  text "28" at 4074.1,-1654.01 h24.55
  text "27.56mil (0.700mm)" at 4331.36,-1654.01 h24.55
  text "PTH" at 4813.59,-1654.01 h24.55
  text "Round" at 5039.49,-1654.01 h24.55
  text "Top Layer - Bottom Layer" at 5358.64,-1654.01 h24.55
  text "Pad" at 5984.04,-1654.01 h24.55
  text "(Mixed)" at 6244.29,-1654.01 h24.55
  text "(Mixed)" at 6701.98,-1654.01 h24.55
  text "-" at 8661.17,-1654.01 h24.55
  text "-" at 9147.48,-1654.01 h24.55
  text "A" at 3832.24,-1664 h27.28
  text "46" at 4074.1,-1715.38 h24.55
  text "33.47mil (0.850mm)" at 4331.36,-1715.38 h24.55
  text "PTH" at 4813.59,-1715.38 h24.55
  text "Round" at 5039.49,-1715.38 h24.55
  text "Top Layer - Bottom Layer" at 5358.64,-1715.38 h24.55
  text "Pad" at 5984.04,-1715.38 h24.55
  text "(Mixed)" at 6244.29,-1715.38 h24.55
  text "(Mixed)" at 6701.98,-1715.38 h24.55
  text "-" at 8661.17,-1715.38 h24.55
  text "-" at 9147.48,-1715.38 h24.55
  text "L" at 3832.24,-1725.38 h27.28
  text "666" at 4074.1,-1776.76 h24.55
  text "10.00mil (0.254mm)" at 4331.36,-1776.76 h24.55
  text "PTH" at 4813.59,-1776.76 h24.55
  text "Round" at 5039.49,-1776.76 h24.55
  text "Top Layer - Bottom Layer" at 5358.64,-1776.76 h24.55
  text "Via" at 5984.04,-1776.76 h24.55
  text "Rounded" at 6244.29,-1776.76 h24.55
  text "(Mixed)" at 6701.98,-1776.76 h24.55
  text "-" at 8661.17,-1776.76 h24.55
  text "-" at 9147.48,-1776.76 h24.55
  text "836 Total" at 4074.1,-1838.14 h24.55
  text "Slot definitions :" at 3848.21,-1909.27 h24.55
  text "Routed Path Length" at 4287.3,-1909.27 h24.55
  text "= Calculated from tool start centre position to tool end centre position." at 4755.03,-1909.27 h24.55
  text "Hole Length" at 4287.3,-1961.99 h24.55
  text "= Routed Path Length + Tool Size = Slot length as defined in the PCB layout" at 4587.32,-1961.99 h24.55
  text ".Layer_Name" at 577,-2658.49 h30
M17 Embedded Cavity:
  text ".Layer_Name" at 577,-2658.49 h30
M18 Embedded Assembly:
  text ".Layer_Name" at 577,-2658.49 h30
M19 Embedded Keepout:
  text ".Layer_Name" at 577,-2658.49 h30

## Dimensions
0,-2200 to 1000,-2200 on M2 Board Dimensions
0,0 to 0,2559.06 on M2 Board Dimensions
0,0 to 10826.77,0 on M2 Board Dimensions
